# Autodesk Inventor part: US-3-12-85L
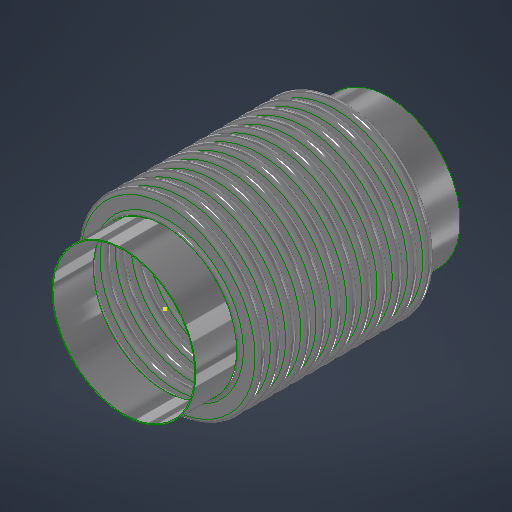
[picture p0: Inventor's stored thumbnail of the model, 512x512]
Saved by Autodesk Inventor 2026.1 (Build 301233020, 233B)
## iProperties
Category: 24 GA (0.024 THICK)
RuleStatus: InUse
Created: 2026-07
Part Number: US-3-12-85L
Project: =STOCK BELLOWS: <Stock Number><SFILL>
Material: ASTM A240-304
Description: =STOCK BELLOWS: <Stock Number>, <SID_> I.D., <SOD_> O.D., <SPLY_> PLY, <Category>, <SNET_CONS> CONS.<PITCH_><STANGENT_> TANGENT<SFILL>
Document SubType Name: Sheet Metal
Designer: LC
Stock Number: U.S-3-12-85L
Surface Area: 659.127 cm^2
Volume: 56.61 cm^3
Sheet Metal Rule: Default
Appearance: STAINLESS STEEL
NET_TUBE: 3.428
COUNTER: 1.500
PBAR: 1.214
PSET: 5.356
PLY: 2
CONS: 2
THK: 0.036
ID: 4.500
OD: 5.500
CONS_: 2
TANGENT: 0.500
PITCH: 0.375
BELLOWS_UPSET: 0.000
NET_CONS: 2
S_CONS: 0
Description_Units: 0
ID_M: 114.30 mm
OD_M: 139.70 mm
THK_M: 0.91 mm
ID_U: 4.500 in
OD_U: 5.500 in
THK_U: 0.036 in
TANGENT2: 0.500
d79: 1.000
d82: 1.000
d83: 26.000
d84: 24.000
d80: 2.571
d81: 10
SID: 2.375
SCONS_: 12
SPITCH: 0.250
SBELLOWS_UPSET: 0.000
SNET_CONS: 12
SS_CONS: 0
SCONS: 8
d174: 8
d177: 0.018
d178: 2.375
d179: 3.000
d180: 0.375
d181: 1.000
d182: 0.000
d190: 8
d191: 1
d192: 1
d193: 8
d194: 0
PART_NUMBER: U.S-3-12-85L
PRESSURE: 85
SIZE: 3.00
STANGENT_: 1.000
d214: 8
d217: 0.030
d218: 6.625
d219: 8.125
d220: 0.500
d221: 1.000
d222: 0.000
d230: 8
d231: 1
d232: 1
d233: 8
d234: 0
STANGENT: 4.000
SPLY_: 1
STHK_: 0.024
SID_: 3.500
SOD_: 4.500
SPITCH_: 0.375
STANGENT__: 1.000
SBELLOWS_UPSET_: 0.000
SDIFF_TAN: 1.000
TAN_TO_TAN: 0.750 in
d252: 2
d275: 2
d287: 0.050
d289: 0.500
d290: 0.000
d263: 2
d265: 1
d268: 2
d269: 0
d286: 2
d288: 1
d291: 2
d292: 0
SOD_NECK: 3 9/16
CFILL: .
SFILL: .
PITCH_: =, <SPITCH_> PITCH,
SREROLL: 0.750
MATTABLE: 20 GA (0.036 THICK)
MESH: ,
CSECT: 2
Author: LC
Keywords: 20 GA (0.036 THICK)
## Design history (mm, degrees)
sketch "Sketch2"
  geometry: L1 (0, -183.595)-(0, 600.956) reference; L2 (58.979, 0)-(57.15, 0); L3 (60.446, -1.467)-(66.554, -1.467); L4 (60.446, -3.296)-(66.554, -3.296); L5 (66.554, -8.058)-(60.446, -8.058); L6 (66.554, -6.229)-(60.446, -6.229); L7 (58.979, -9.525)-(57.15, -9.525); L8 (60.446, 0)-(60.446, -9.525); L9 (66.554, -4.762)-(69.85, -4.763); L10 (57.15, 0)-(57.15, -9.525); L11 (20.376, 102.841)-(20.376, 101.926); L12 (58.262, 488.877)-(58.262, 349.177); L13 (58.262, 479.352)-(58.262, 339.652); L14 (93.133, -58.817)-(93.133, -71.517); L15 (118.746, -66.401)-(118.746, -66.401); L16 (66.554, -6.229)-(66.554, -8.058); L17 (60.446, -6.229)-(60.446, -8.058); L18 (60.446, -7.144)-(66.554, -7.144); L19 (69.85, 0)-(69.85, -9.525); L20 (-66.554, -6.229)-(-66.554, -8.058); L21 (-66.554, -1.467)-(-60.446, -1.467); L22 (-66.554, -3.296)-(-60.446, -3.296); L23 (-60.446, -6.229)-(-66.554, -6.229); L24 (-66.554, -7.144)-(-60.446, -7.144); L25 (-60.446, -8.058)-(-66.554, -8.058); L26 (-60.446, -6.229)-(-60.446, -8.058); L27 (-57.15, -2.522)-(-57.15, -12.047); L28 (-60.446, -4.763)-(-57.15, -4.763); L29 (-66.554, 3.828)-(-66.554, -9.525); L30 (-68.021, 0)-(-69.85, 0); L31 (-69.85, 0)-(-69.85, -9.525); L32 (-68.021, -9.525)-(-69.85, -9.525); A1 r 1.467 centre (60.446, 0) between (58.979, 0) and (60.446, -1.467); A2 r 3.296 centre (60.446, 0) between (57.15, 0) and (60.446, -3.296); A3 r 3.296 centre (66.554, -4.762) between (66.554, -8.058) and (66.554, -1.467); A4 r 1.467 centre (66.554, -4.762) between (66.554, -6.229) and (66.554, -3.296); A5 r 1.467 centre (60.446, -9.525) between (60.446, -8.058) and (58.979, -9.525); A6 r 3.296 centre (60.446, -9.525) between (60.446, -6.229) and (57.15, -9.525); A7 r 2.381 centre (66.554, -4.762) between (66.554, -7.144) and (68.936, -4.762); A8 r 2.381 centre (60.446, -9.525) between (60.446, -7.144) and (58.064, -9.525); A9 r 1.467 centre (-66.554, -9.525) between (-66.554, -8.058) and (-68.021, -9.525); A10 r 1.467 centre (-60.446, -4.763) between (-60.446, -6.229) and (-60.446, -3.296); A11 r 2.381 centre (-60.446, -4.763) between (-60.446, -7.144) and (-58.064, -4.763); A12 r 3.296 centre (-60.446, -4.763) between (-60.446, -8.058) and (-60.446, -1.467); A13 r 2.381 centre (-66.554, -9.525) between (-66.554, -7.144) and (-68.936, -9.525); A14 r 3.296 centre (-66.554, -9.525) between (-66.554, -6.229) and (-69.85, -9.525); A15 r 1.467 centre (-66.554, 0) between (-68.021, 0) and (-66.554, -1.467); A16 r 3.296 centre (-66.554, 0) between (-69.85, 0) and (-66.554, -3.296); 10 further points
  constraints: 62 end point, 38 point on circle, 20 tangent, 16 centre point, 12 parallel, 9 midpoint, 7 vertical, 6 coincident, 6 concentric, 6 point on line, 4 equal radius, 4 perpendicular, 3 horizontal, 1 collinear, 1 horizontal alignment, 10 other
  dimensions: "THK" = 0.9144 distance of L11.start L11.end; "ID" = 114.3 distance of L11.end point (20.376, -12.374); "OD" = 139.7 distance of L12.start L12.end; "PITCH" = 9.525 distance of L12.start L13.start; "TANGENT" = 12.7 distance of L14.start L14.end; "BELLOWS_UPSET" = 0 distance of L15.start L15.end; "d43" = 114.3 diameter of L10 L1 (= ID); "d44" = 139.7 diameter of L9.end L1 (= OD); "d45" = 1.8288 distance between parallel lines of L5 L6 (computed from THK, PLY); "d46" = 3.29565 radius of A3 (computed from PITCH, THK, PLY); "UPSET_PITCH" = 9.525 distance of L2.end L7.end (derived); "SIDEWALL_ANGLE" = 0 deg angle of L3 L9 (derived); "CON_GAP" = 2.9337 distance of point (60.446, -6.229) point (60.446, -3.296) (derived); "TAN1" = 3.74046 dimension on A8 (derived); "TAN2" = 3.74046 dimension on A7 (derived); "LEG1" = 6.1087 distance of L18.start L18.end (derived); "d278" = 1.8288 distance between parallel lines of L25 L23 (derived); "d279" = 3.29565 radius of A12 (derived); "d280" = 9.525 distance of L30.end L31.end (derived); "d281" = 360 deg dimension on L21 L28 (derived); "d282" = 2.9337 distance of point (-66.554, -6.229) point (-66.554, -3.296) (derived); "d283" = 3.74046 dimension on A13 (derived); "d284" = 3.74046 dimension on A11 (derived); "d285" = 6.1087 distance of L24.start L24.end (derived); "d293" = 114.3 diameter of L27 L1 (derived); "d294" = 139.7 diameter of L31 L1 (derived)
  node "Sketch Rectangular Pattern1" dims "d31" = 25.4, "ID" = 114.3
  node "Sketch Rectangular Pattern2" dims "d39" = 25.4, "PITCH" = 9.525
revolve "CONS" stored, may be unused: angle "d48" = 90 deg
node "BELLOW MIDPLANE"
pattern_linear "Rectangular Pattern2" dims "d52" = 9.525 (= UPSET_PITCH)
sketch "Sketch5"
  geometry: C1 r 58.979 at (0, 0) reference; C2 r 57.15 at (0, 0) reference
extrude "TANGENT" new body sketch "Sketch5" distance "d53" = 12.7 (= TANGENT); taper "d54" = 0 deg
revolve "SAMETAN" stored, may be unused: angle "d65" = 90 deg
revolve "DIFFTAN" stored, may be unused: angle "d70" = 90 deg
sketch "Sketch9"
  geometry: L1 (58.391, 0)-(-58.391, 0) reference; L2 (0, -17.78)-(0, 17.78) reference; L3 (41.708, 0)-(-41.708, 0); L4 (41.708, -11.906)-(41.708, 11.906); L5 (29.008, -11.906)-(29.008, 11.906); L6 (15.418, 11.906)-(15.418, -11.906); L7 (-29.008, -11.906)-(-29.008, 11.906); L8 (-41.708, -11.906)-(-41.708, 11.906); L9 (40.914, -11.906)-(40.914, 11.906); L10 (41.708, -11.906)-(40.914, -11.906); L11 (41.708, 11.906)-(40.914, 11.906); L12 (15.815, 11.906)-(15.022, 11.906); L13 (15.022, 11.906)-(15.022, -11.906); L14 (15.022, -11.906)-(15.815, -11.906); L15 (15.815, -11.906)-(15.815, 11.906); L16 (-15.815, 11.906)-(-15.815, -11.906); L17 (-15.418, 11.906)-(-15.418, -11.906); L18 (-15.815, -11.906)-(-15.022, -11.906); L19 (-15.022, -11.906)-(-15.022, 11.906); L20 (-15.022, 11.906)-(-15.815, 11.906); L21 (-41.708, -11.906)-(-40.914, -11.906); L22 (-40.914, -11.906)-(-40.914, 11.906); L23 (-40.914, 11.906)-(-41.708, 11.906); L24 (-41.708, 11.906)-(-41.708, -11.906); L25 (41.708, -0.397)-(-41.708, -0.397); L26 (-41.708, -0.397)-(-41.708, 0.397); L27 (-41.708, 0.397)-(41.708, 0.397); L28 (41.708, 0.397)-(41.708, -0.397); L29 (-41.708, 11.906)-(41.708, 11.906); L30 (41.708, 11.906)-(41.708, 12.7); L31 (41.708, 12.7)-(-41.708, 12.7); L32 (-41.708, 12.7)-(-41.708, 11.906); L33 (41.708, -11.906)-(-41.708, -11.906); L34 (-41.708, -11.906)-(-41.708, -12.7); L35 (-41.708, -12.7)-(41.708, -12.7); L36 (41.708, -12.7)-(41.708, -11.906); 30 further points
  constraints: 68 end point, 13 midpoint, 13 parallel, 8 horizontal, 7 perpendicular, 6 equal length, 3 point on line, 2 vertical, 14 other
  dimensions: "d115" = 23.8125 distance of L4.start L4.end (derived); "d116" = 12.7 distance between parallel lines of L4 L5 (derived); "d117" = 13.58962 distance between parallel lines of L5 L6 (derived); "d125" = 44.42645 distance between parallel lines of L7 L6 (derived); "d127" = 12.7 distance between parallel lines of L8 L7 (derived); "d128" = 26.28962 distance between parallel lines of L6 L4 (derived); "d130" = 83.41607 distance between parallel lines of L8 L4 (derived); "RULER_THK" = 0.79375 distance between parallel lines of L4 L9; "d135" = 0.79375 distance of L13.end L14.end (derived); "d138" = 30.83684 distance of L13.end L16.end (derived); "d143" = 0.79375 distance of L22.end L8.end (derived); "d144" = 0.79375 distance between parallel lines of L27 L25 (derived)
extrude "RULER" join sketch "Sketch9" distance "d149" = 0.79375 (derived); taper "d150" = 0 deg
extrude "BARS" join sketch "Sketch9" distance "d151" = 0.79375 (derived); taper "d152" = 0 deg
pattern_linear "Rectangular Pattern4" dims "d155" = 30.83684 (derived)
sketch "Sketch13"
  geometry: L1 (93.149, -52.467)-(93.149, -77.867); L2 (45.06, 0)-(44.45, 0); L3 (45.06, -9.525)-(44.45, -9.525); L4 (54.464, -7.449)-(47.136, -7.449); L5 (54.464, -6.839)-(47.136, -6.839); L6 (54.464, -4.762)-(57.15, -4.762); L7 (47.136, -2.076)-(54.464, -2.076); L8 (47.136, 0)-(47.136, -9.525); L9 (44.45, 0)-(44.45, -9.525); L10 (58.254, -360.964)-(58.254, -475.264); L11 (58.254, -370.489)-(58.254, -484.789); L12 (58.254, -389.539)-(58.254, -503.839); L13 (58.254, -399.064)-(58.254, -513.364); L14 (58.254, -408.589)-(58.254, -522.889); L15 (58.254, -418.114)-(58.254, -532.414); L16 (58.254, -427.639)-(58.254, -541.939); L17 (58.254, -380.014)-(58.254, -494.314); L18 (20.376, 102.536)-(20.376, 101.926); L19 (47.136, -2.686)-(54.464, -2.686); L20 (0, -654.548)-(0, 228.539) reference; L21 (-23.752, 0)-(142.514, 0) reference; A1 r 2.076 centre (47.136, 0) between (45.06, 0) and (47.136, -2.076); A2 r 2.076 centre (47.136, -9.525) between (47.136, -7.449) and (45.06, -9.525); A3 r 2.686 centre (47.136, -9.525) between (47.136, -6.839) and (44.45, -9.525); A4 r 2.076 centre (54.464, -4.762) between (54.464, -6.839) and (54.464, -2.686); A5 r 2.686 centre (54.464, -4.762) between (54.464, -7.449) and (54.464, -2.076); A6 r 2.686 centre (47.136, 0) between (44.45, 0) and (47.136, -2.686); 6 further points; 1 other entity
  constraints: 38 end point, 15 point on circle, 9 tangent, 6 centre point, 6 parallel, 5 vertical alignment, 4 point on line, 4 vertical, 3 coincident, 3 concentric, 2 collinear, 2 equal radius, 1 horizontal, 1 perpendicular, 23 other
  dimensions: "SBELLOWS_UPSET_" = 0 distance of point (118.762, -66.401) point (118.762, -66.401); "STOTAL_THK_BELLOW__" = 0.6096 distance between parallel lines of L4 L5 (derived); "d224" = 2.68605 radius of A5 (derived); "d225" = 9.525 distance of L2.end L3.end (derived); "SSIDEWALL_ANGLE_" = 360 deg dimension on L7 L6 (derived); "SSCON_GAP_" = 4.1529 distance of point (47.136, -6.839) point (47.136, -2.686) (derived); "d235" = 88.9 diameter of L9 L20 (derived); "d236" = 114.3 diameter of L6.end L20 (derived)
  node "Sketch Rectangular Pattern4" dims "d228" = 25.4
  node "Sketch Rectangular Pattern5" dims "d229" = 25.4
revolve "SBELLOW" stored, may be unused: angle "d197" = 90 deg
pattern_linear "Rectangular Pattern5" dims "d204" = 9.525 (derived)
revolve "STANGENT" stored, may be unused: angle "d240" = 90 deg
revolve "SSAMETAN" stored, may be unused: angle "d241" = 90 deg
revolve "SDIFFTAN" stored, may be unused: angle "d246" = 90 deg
revolve "INVCON" stored, may be unused: angle "d295" = 90 deg
pattern_linear "Rectangular Pattern6" dims "d298" = 9.525 (derived)
revolve "INVTANGENT" stored, may be unused: angle "d302" = 90 deg
revolve "INVSAMETAN" stored, may be unused: angle "d307" = 90 deg
revolve "INVDIFFTAN" stored, may be unused: angle "d312" = 90 deg
sketch "ID BELLOW MOUNT CALC"
  geometry: L1 (44.45, 0)-(38.1, 0); L2 (38.1, 0)-(38.1, 12.7); L3 (38.1, 12.7)-(44.45, 12.7); L4 (44.45, 12.7)-(44.45, 0); L5 (36.513, 12.7)-(34.684, 12.7); L6 (34.684, 12.7)-(34.684, 0); L7 (34.684, 0)-(36.513, 0); L8 (36.513, 0)-(36.513, 12.7); L9 (0, -2.54)-(0, 15.24) reference; L10 (-8.89, 0)-(53.34, 0) reference; 1 further point
  constraints: 16 end point, 5 parallel, 2 collinear, 2 horizontal, 2 perpendicular
  dimensions: "d314" = 12.7 distance of L5.end L6.end (derived); "d315" = 1.8288 distance of L5.start L5.end (derived); "IG" = 1.5875 distance between parallel lines of L2 L8; "PIPE_OD" = 88.9 diameter of L4 L9; "PIPE_WALL" = 6.35 distance of L2.end L3.end; "ID_MT_BELLOW" = 69.3674 diameter of L6 L9 (derived)
revolve "CFILL" stored, may be unused: angle "d320" = 90 deg
pattern_linear "Rectangular Pattern7" dims "d323" = 9.525 (derived)
revolve "SFILL" stored, may be unused: angle "d324" = 90 deg
pattern_linear "Rectangular Pattern8" dims "d327" = 9.525 (derived)
node "STOCK BELLOW MIDPLANE"
sketch "Sketch21"
  geometry: L1 (0, -100.013)-(0, 100.013) reference; L2 (-100.013, 0)-(100.013, 0) reference; L3 (-0.099, 71.437)-(0.099, 71.437); L4 (0.099, 71.437)-(0.099, 55.562); L5 (0.099, 55.562)-(-0.099, 55.562); L6 (-0.099, 55.562)-(-0.099, 71.437); C1 r 55.562 at (0, 0); C2 r 71.437 at (0, 0); 3 further points
  constraints: 8 end point, 2 centre point, 2 coincident, 2 parallel, 2 tangent, 1 horizontal, 1 perpendicular, 1 other
  dimensions: "d329" = 111.125 diameter of C1 (derived); "d330" = 142.875 diameter of C2 (derived); "d331" = 0.19844 distance of L3.start L3.end
extrude "CLAMSHELL" cut sketch "Sketch21" extent not by distance; stored distance "d332" = 0; taper "d333" = 0 deg
pattern_circular "Circular Pattern1" dims angle "d335" = 180 deg (derived)
node "BELLOW"
sketch "Sketch6"
  geometry: L1 (-19.05, 58.979)-(-6.35, 58.979); L2 (-6.35, 58.979)-(-6.35, 57.15); L3 (-6.35, 57.15)-(-19.05, 57.15); L4 (-19.05, 57.15)-(-19.05, 58.979); L5 (2.54, 0)-(-59.69, 0) reference; L6 (-38.1, -108.388)-(-38.1, 156.601) reference; 1 further point
  constraints: 8 end point, 2 parallel, 1 horizontal, 1 perpendicular
  dimensions: "d61" = 12.7 distance of L2.end L3.end (derived); "d62" = 1.8288 distance of L1.end L2.end (derived); "d63" = 114.3 diameter of L3 L5 (derived); "d64" = 19.05 distance between parallel lines of L4 L6 (derived)
sketch "Sketch12"
  geometry: 1 further point
sketch "Sketch14"
  geometry: L1 (-25.4, 45.06)-(0, 45.06); L2 (0, 45.06)-(0, 44.45); L3 (0, 44.45)-(-25.4, 44.45); L4 (-25.4, 44.45)-(-25.4, 45.06); L5 (5.08, 0)-(-30.48, 0) reference; L6 (0, -8.89)-(0, 53.34) reference; 1 further point
  constraints: 8 end point, 2 parallel, 1 collinear, 1 horizontal, 1 perpendicular
  dimensions: "d237" = 0.6096 distance of L3.end L1.start (derived); "d238" = 88.9 diameter of L3 L5 (derived); "d239" = 25.4 distance of L1.start L1.end (derived); "SOD_NECK" = 90.1192 diameter of L1 L5 (derived)
sketch "Sketch15"
  geometry: L1 (-8.89, 0)-(53.34, 0) reference; L2 (44.45, -114.3)-(45.06, -114.3); L3 (45.06, -114.3)-(45.06, -139.7); L4 (45.06, -139.7)-(44.45, -139.7); L5 (44.45, -139.7)-(44.45, -114.3); L6 (0, -170.18)-(0, 43.18) reference; 1 further point
  constraints: 8 end point, 2 parallel, 1 horizontal, 1 perpendicular
  dimensions: "d205" = 25.4 distance of L4.end L2.start (derived); "d206" = 0.6096 distance of L3.end L4.end (derived); "d207" = 88.9 diameter of L5 L6 (derived); "d208" = 114.3 distance between parallel lines of L1 L2 (derived)
node "TANGENT_"
node "SAME_TAN"
sketch "Sketch8"
  geometry: L1 (58.979, -19.05)-(57.15, -19.05); L2 (57.15, -19.05)-(57.15, -31.75); L3 (57.15, -31.75)-(58.979, -31.75); L4 (58.979, -31.75)-(58.979, -19.05); L5 (0, -40.64)-(0, 21.59) reference; L6 (-108.388, 0)-(156.601, 0) reference; 1 further point
  constraints: 8 end point, 2 parallel, 1 horizontal, 1 perpendicular
  dimensions: "d66" = 114.3 diameter of L2 L5 (derived); "TOTAL_THK_BELLOW" = 1.8288 distance of L2.end L3.end (derived); "d68" = 19.05 distance between parallel lines of L1 L6 (derived); "d69" = 12.7 distance of L1.end L2.end (derived)
node "DIFF_TAN"
node "Sketch Rectangular Pattern3" dims "d138" = 30.83684 (derived), "d141" = 25.4
node "SBELLOW_"
node "STANGENT_"
node "SSAME_TAN"
sketch "Sketch16"
  geometry: L1 (45.06, -114.3)-(44.45, -114.3); L2 (44.45, -114.3)-(44.45, -139.7); L3 (44.45, -139.7)-(45.06, -139.7); L4 (45.06, -139.7)-(45.06, -114.3); L5 (0, -170.18)-(0, 43.18) reference; L6 (-8.89, 0)-(53.34, 0) reference; 1 further point
  constraints: 8 end point, 2 parallel, 1 horizontal, 1 perpendicular
  dimensions: "SDIFF_TAN" = 25.4 distance of L3.end L1.start; "d243" = 0.6096 distance of L2.end L3.end (derived); "d244" = 114.3 distance between parallel lines of L1 L6 (derived); "d245" = 88.9 diameter of L2 L5 (derived)
node "SDIFF_TAN"
body "Solid15"
sketch "Sketch17"
  geometry: L1 (69.85, 12.7)-(68.021, 12.7); L2 (68.021, 12.7)-(68.021, 0); L3 (68.021, 0)-(69.85, 0); L4 (69.85, 0)-(69.85, 12.7); L5 (0, -2.54)-(0, 15.24) reference; L6 (-13.97, 0)-(83.82, 0) reference; 2 further points
  constraints: 8 end point, 2 parallel, 1 horizontal, 1 midpoint, 1 perpendicular, 1 point on line
  dimensions: "INVTANGENT" = 12.7 distance of L3.end L1.start (derived); "d300" = 1.8288 distance of L1.start L1.end (derived); "d301" = 139.7 diameter of L4 L5 (derived)
body "Solid16"
sketch "Sketch18"
  geometry: L1 (69.85, -19.05)-(68.021, -19.05); L2 (68.021, -19.05)-(68.021, -31.75); L3 (68.021, -31.75)-(69.85, -31.75); L4 (69.85, -31.75)-(69.85, -19.05); L5 (-13.97, 0)-(83.82, 0) reference; L6 (0, -40.64)-(0, 21.59) reference; 1 further point
  constraints: 8 end point, 2 parallel, 1 horizontal, 1 perpendicular
  dimensions: "d303" = 19.05 distance between parallel lines of L1 L5 (derived); "d304" = 12.7 distance of L3.end L1.start (derived); "d305" = 1.8288 distance of L2.end L3.end (derived); "d306" = 139.7 diameter of L4 L6 (derived)
body "Solid17"
sketch "Sketch19"
  geometry: L1 (69.85, -19.05)-(68.021, -19.05); L2 (68.021, -19.05)-(68.021, -31.75); L3 (68.021, -31.75)-(69.85, -31.75); L4 (69.85, -31.75)-(69.85, -19.05); L5 (0, -40.64)-(0, 21.59) reference; L6 (-13.97, 0)-(83.82, 0) reference; 1 further point
  constraints: 8 end point, 2 parallel, 1 horizontal, 1 perpendicular
  dimensions: "d308" = 12.7 distance of L1.end L2.end (derived); "d309" = 139.7 diameter of L4 L5 (derived); "d310" = 1.8288 distance of L2.end L3.end (derived); "d311" = 19.05 distance between parallel lines of L1 L6 (derived)
body "Solid18"
body "Solid19"
body "Solid20"
other parameters: "BMPL" = -57.15, "PSET" = 136.0424 (computed from OD, THK, PLY) [user parameter], "PBAR" = 30.83684 (= 0.570796 x PITCH + OD - ID) [user parameter; used in 1 equation term], "COUNTER" = 15 [user parameter], "NET_TUBE" = 87.07367 (computed from CONS_, PBAR, TANGENT) [user parameter], "S_CONS" = 0 [user parameter; used in 1 equation term], "ID_M" = 114.3 (= ID) [user parameter], "OD_M" = 139.7 (= OD) [user parameter], "THK_M" = 0.9144 (= THK) [user parameter], "ID_U" = 114.3 (= ID) [user parameter], "OD_U" = 139.7 (= OD) [user parameter], "THK_U" = 0.9144 (= THK) [user parameter], "D_UNITS" = 0 [user parameter], "TANGENT2" = 12.7 [user parameter], "TAN_TO_TAN" = 19.05 [user parameter], "OD_NECK" = 117.9576 [user parameter], "d79" = 25.4, "d80" = 65.29823 [user parameter], "d82" = 25.4, "d83" = 660.4, "d84" = 609.6, "sa_0" = 4, "FRAME_THK" = 0.79375 [user parameter], "CON_FLAT" = 13.58962 [user parameter], "SID" = 60.325 [user parameter], "SPITCH" = 6.35 [user parameter], "STANGENT_" = 25.4 [user parameter], "SBELLOWS_UPSET" = 0 [user parameter], "SS_CONS" = 0 [user parameter], "STAN_TO_TAN_" = 114.3 [user parameter], "d100" = 0.6096 [user parameter], "d191" = 25.4 [user parameter], "d194" = 0 [user parameter], "STANGENT" = 101.6 [user parameter], "d234" = 0 [user parameter], "SUPSET_PITCH_" = 9.525 [user parameter], "d269" = 0 [user parameter], "d287" = 1.27, "d289" = 12.7, "d290" = 0, "d292" = 0 [user parameter], "Thickness" = 3.048 (derived), "KFactor" = 4.4, "BendRadius" = 3.048 (derived), "BendReliefWidth" = 3.048 (derived), "BendReliefDepth" = 1.524 (derived), "CornerReliefSize" = 12.192 (derived), "SeamGap" = 0.00508, "MinimumRemnant" = 6.096 (derived), "TransitionRadius" = 3.048 (derived), "JacobiRadiusSize" = 3.048 (derived), "GapSize" = 3.048 (derived), "SREROLL" = 19.05 [user parameter], "CUR_STK_PITCH" = 9.525 [user parameter], "d328" = -57.15 (derived), "CSECTDEG" = 180 deg [user parameter]
